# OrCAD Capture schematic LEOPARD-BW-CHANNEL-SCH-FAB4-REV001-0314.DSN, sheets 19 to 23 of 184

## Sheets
19 160_PVTT_EF_MOSFET: size A3; title: PVTT_EF_MOSFET
20 159_PVDDQ_EF_MOSFET: size C; title: PVDDQ_EF_MOSFET
21 158_PVDDQ_EF_Controller: size C; title: PVDQ_EF_CONTROLLER
22 157_PVPP_CD_TPS53318: size A3; title: PVPP_CD_TPS53318
23 156_PVDDQ_CD_Decoupling: size A3; title: PVDDQ_CD_DECOUPLING

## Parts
sheet 156_PVDDQ_CD_Decoupling
PC415  SCD1U25V5KX-1GP  [C805H54]
PC416  SC1U25V6KX-2GP  [C1206H45]
PC417  SCD1U25V5KX-1GP  [C805H54]
PC418  SE470UF2VDM-GP  [CT7343H83]
PC419  SE470UF2VDM-GP  [CT7343H83]
PC420  SE470UF2VDM-GP  [CT7343H83]
PC421  SE470UF2VDM-GP  [CT7343H83]
PC422  SC47U4V5MX-2-GP  [C805H58]
PC423  SC47U4V5MX-2-GP  [C805H58]
PC424  SC47U4V5MX-2-GP  [C805H58]
PC425  SC47U4V5MX-2-GP  [C805H58]
PC426  SC22U6D3V5MX-5-GP  [C805H56]
PC427  SC22U6D3V5MX-5-GP  [C805H56]
PC428  SC22U6D3V5MX-5-GP  [C805H56]
PC429  SC22U6D3V5MX-5-GP  [C805H56]
PC430  SC22U6D3V5MX-5-GP  [C805H56]
PC431  SC22U6D3V5MX-5-GP  [C805H56]
PC432  SC22U6D3V5MX-5-GP  [C805H56]
PC433  SC22U6D3V5MX-5-GP  [C805H56]
PC434  SC22U6D3V5MX-5-GP  [C805H56]
PC435  SC22U6D3V5MX-5-GP  [C805H56]
PC436  SC22U6D3V5MX-5-GP  [C805H56]
PC437  SC22U6D3V5MX-5-GP  [C805H56]
PC438  SC22U6D3V5MX-5-GP  [C805H56]
PC439  SC22U6D3V5MX-5-GP  [C805H56]
PC440  SC22U6D3V5MX-5-GP  [C805H56]
PC441  SC22U6D3V5MX-5-GP  [C805H56]
PC442  SC22U6D3V5MX-5-GP  [C805H56]
PC443  SC22U6D3V5MX-5-GP  [C805H56]
PC444  SC22U6D3V5MX-5-GP  [C805H56]
PC445  SC22U6D3V5MX-5-GP  [C805H56]
PC446  SC22U6D3V5MX-5-GP  [C805H56]
PC447  SC22U6D3V5MX-5-GP  [C805H56]
PC448  SC22U6D3V5MX-5-GP  [C805H56]
PC449  SC22U6D3V5MX-5-GP  [C805H56]
PC450  SC22U6D3V5MX-5-GP  [C805H56]
PC451  SC22U6D3V5MX-5-GP  [C805H56]
PC452  SC22U6D3V5MX-5-GP  [C805H56]
PC453  SC22U6D3V5MX-5-GP  [C805H56]
PC454  SC22U6D3V5MX-5-GP  [C805H56]
PC455  SC22U6D3V5MX-5-GP  [C805H56]
PC456  SC22U6D3V5MX-5-GP  [C805H56]
PC457  SC22U6D3V5MX-5-GP  [C805H56]
PC458  SC22U6D3V5MX-5-GP  [C805H56]
PC459  SC22U6D3V5MX-5-GP  [C805H56]
PC460  SC22U6D3V5MX-5-GP  [C805H56]
PC461  SC22U6D3V5MX-5-GP  [C805H56]
PC462  SC22U6D3V5MX-5-GP  [C805H56]
PC463  SC22U6D3V5MX-5-GP  [C805H56]
PC464  SC22U6D3V5MX-5-GP  [C805H56]
PC465  SC22U6D3V5MX-5-GP  [C805H56]
PC845  SC22U6D3V5MX-5-GP  [C805H56]
PC846  SC22U6D3V5MX-5-GP  [C805H56]
PC847  SC22U6D3V5MX-5-GP  [C805H56]
PC848  SC22U6D3V5MX-5-GP  [C805H56]
PC849  SC22U6D3V5MX-5-GP  [C805H56]
PC850  SC22U6D3V5MX-5-GP  [C805H56]
PC855  SC22U6D3V5MX-5-GP  [C805H56]
PC856  SC22U6D3V5MX-5-GP  [C805H56]
PC997  SC22U6D3V5MX-5-GP  [C805H56]
PC998  SC22U6D3V5MX-5-GP  [C805H56]
PC999  SC22U6D3V5MX-5-GP  [C805H56]
PL22  IND-65NH-GP  [L4038-1412H158]
PR255  33R3F-L-GP  [R603H22]
PR256  0R2F-L-GP  [R402H16]
PR257  0R2F-L-GP  [R402H16]
PTC6  E270U16VM-28-GP  [ECAP-100D6D3H363]
sheet 157_PVPP_CD_TPS53318
PC466  SC10U16V5KX-1-GP  [C805H54]
PC467  SC10U16V5KX-1-GP  [C805H54]
PC468  SC10U16V5KX-1-GP  [C805H54]
PC469  SC10U16V5KX-1-GP  [C805H54]
PC470  SCD1U16V3KX-3GP  [C603H36]
PC471  SC4D7U25V5KX-1-GP  [C805H58]
PC472  SCD1U50V3KX-GP  [C603H36]
PC473  SC2K2P50V3KX-GP  [C603]
PC474  SC1U10V2KX-4-GP  [C402H22]
PC475  SCD1U16V2KX-3GP  [C402H22]
PC476  SC1KP50V2KX-1GP  [C402H22]
PC477  SCD1U16V3KX-3GP  [C603H36]
PC478  SC22U6D3V5MX-5-GP  [C805H56]
PC479  SC47U4V5MX-2-GP  [C805H58]
PC480  SC47U4V5MX-2-GP  [C805H58]
PC481  SC47U4V5MX-2-GP  [C805H58]
PC482  SC47U4V5MX-2-GP  [C805H58]
PC483  SC47U4V5MX-2-GP  [C805H58]
PC484  SC47U4V5MX-2-GP  [C805H58]
PC1039  SC1U10V2KX-4-GP  [C402H22]
PD23  BZT52-C3V3S-GP  [SOD323AKH38]
PL23  BLM21PG220SN1DGP  [L20125H42]
PL24  IND-2D2UH-242-GP  [L7165-1732H119]
PR258  2D2R3-1-U-GP  [R603H22]
PR259  3D01R5F-GP  [R805H24]
PR260  0R2J-2-GP  [R402H16]
PR262  3K9R2F-GP  [R402H16]
PR263  10R3F-GP  [R603H22]
PR264  3D01R5F-GP  [R805H24]
PR265  100KR2F-L1-GP  [R402H16]
PR266  100KR2F-L1-GP  [R402H16]
PR267  100KR2F-L1-GP  [R402H16]
PR268  866KR2F-GP  [R402H16]
PR269  619KR2F-GP  [R402H16]
PR270  31K6R2F-GP  [R402H16]
PR271  10KR2F-2-GP  [R402H16]
PR272  0R3J-0-U-GP  [R603H22]
PR644  10KR2F-2-GP  [R402H16]
PR800  0R2J-2-GP  [R402H16]
PU24  TPS53318DQPR-GP  [DFN22G6050-G6133H60]
sheet 158_PVDDQ_EF_Controller
PC1423  SC1KP50V2KX-1GP  [C402H22]
PC1424  SC1U10V2KX-4-GP  [C402H22]
PC1425  SCD1U16V2KX-3GP  [C402H22]
PC1426  SC1U10V2KX-4-GP  [C402H22]
PC1427  SCD1U16V2KX-3GP  [C402H22]
PC1431  SC220P50V2KX-3GP  [C402H22]
PC1432  SCD47U25V3KX-3-GP  [C603H36]
PC1433  SC220P50V2KX-3GP  [C402H22]
PC1434  SC220P50V2JN-3GP  [C402H22]
PC1468  SC220P50V2JN-3GP  [C402H22]
PC1622  SC220P50V2JN-3GP  [C402H22]
PC7335  SCD47U6D3V2KX-1-GP  [C402H22]
PC7336  SCD47U6D3V2KX-1-GP  [C402H22]
PQ13  NST3906F3T5G-GP-U  [SOT-1123CBE1006-1H16]
PR1940  0R2J-2-GP  [R402H16]
PR2058  19K1R2F-GP  [R402H16]
PR2059  1KR2F-3-GP  [R402H16]
PR2060  0R2J-2-GP  [R402H16]
PR2063  1KR2F-3-GP  [R402H16]
PR2066  1KR2F-3-GP  [R402H16]
PR2067  0R2J-2-GP  [R402H16]
PR2068  0R2J-2-GP  [R402H16]
PR2069  10R3F-GP  [R603H22]
PR2071  0R2J-2-GP  [R402H16]
PR2072  0R0402-PAD-1-GP  [0R0402-PAD]
PR2075  16KR2F-GP  [R402H16]
PR2076  4K02R2F-GP  [R402H16]
PR2077  549R2F-GP  [R402H16]
PR2078  16KR2F-GP  [R402H16]
PR2079  0R2J-2-GP  [R402H16]
PR2080  0R2J-2-GP  [R402H16]
PR2081  150R2F-1-GP  [R402H16]
PR2082  0R2J-2-GP  [R402H16]
PR2083  10R3F-GP  [R603H22]
PR2084  0R0402-PAD-1-GP  [0R0402-PAD]
PTP5  TP20B24R10-B-GP  [TP20B24R10-B]
PU25  PX3244HDM-1-GP  [QFN40J5-G3D75H36]
sheet 159_PVDDQ_EF_MOSFET
PC1546  SCD47U25V3KX-3-GP  [C603H36]
PC1547  SC10U16V5KX-1-GP  [C805H54]
PC1548  SC10U16V5KX-1-GP  [C805H54]
PC1549  SC10U16V5KX-1-GP  [C805H54]
PC1550  SCD1U16V2KX-3GP  [C402H22]
PC1551  SC1U25V3KX-GP  [C603H36]
PC1552  SCD1U16V2KX-3GP  [C402H22]
PC1553  SC1U10V2KX-4-GP  [C402H22]
PC1554  SCD22U16V2KX-GP  [C402H22]
PC1555  SC1U10V2KX-4-GP  [C402H22]
PC1556  SCD47U25V3KX-3-GP  [C603H36]
PC1557  SC10U16V5KX-1-GP  [C805H54]
PC1558  SC10U16V5KX-1-GP  [C805H54]
PC1559  SC10U16V5KX-1-GP  [C805H54]
PC1560  SCD1U16V2KX-3GP  [C402H22]
PC1561  SC1U25V3KX-GP  [C603H36]
PC1562  SCD1U16V2KX-3GP  [C402H22]
PC1563  SC1U10V2KX-4-GP  [C402H22]
PC1564  SCD22U16V2KX-GP  [C402H22]
PC1565  SC1U10V2KX-4-GP  [C402H22]
PG73  COPPER-CLOSE-GP-U  [CON2C-U]
PG74  COPPER-CLOSE-GP-U  [CON2C-U]
PG79  COPPER-CLOSE-GP-U  [CON2C-U]
PG80  COPPER-CLOSE-GP-U  [CON2C-U]
PL88  IND-150NH-15-GP  [L102078-254224H296]
PL95  IND-150NH-15-GP  [L102078-254224H296]
PR38  0R2J-2-GP  [R402H16]
PR39  0R2J-2-GP  [R402H16]
PR56  0R2J-2-GP  [R402H16]
PR57  0R2J-2-GP  [R402H16]
PR2214  1R2F-GP  [R402H16]
PR2249  1R2F-GP  [R402H16]
PR2250  10KR2F-2-GP  [R402H16]
PR2251  10KR2F-2-GP  [R402H16]
PR2271  0R3J-6-GP  [R603H22]
PR2274  0R3J-6-GP  [R603H22]
PR6653  562R2F-GP  [R402H16]
PR6654  562R2F-GP  [R402H16]
PR6667  562R2F-GP  [R402H16]
PR6668  562R2F-GP  [R402H16]
PTP33  TPAD24  [TPAD24]
PTP34  TPAD24  [TPAD24]
PTP47  TPAD24  [TPAD24]
PTP48  TPAD24  [TPAD24]
PU191  TDA21232-GP  [QFN31G5-G4P-7H38]
PU198  TDA21232-GP  [QFN31G5-G4P-7H38]
sheet 160_PVTT_EF_MOSFET
PC518  SC1U10V2KX-4-GP  [C402H22]
PC519  SCD22U16V2KX-GP  [C402H22]
PC521  SCD22U16V2KX-GP  [C402H22]
PC523  SC1U25V3KX-GP  [C603H36]
PC526  SC10U16V5KX-1-GP  [C805H54]
PC527  SC10U16V5KX-1-GP  [C805H54]
PC528  SCD47U25V3KX-3-GP  [C603H36]
PC529  SC220P50V2JN-3GP  [C402H22]
PC530  SC47U4V5MX-2-GP  [C805H58]
PC531  SC47U4V5MX-2-GP  [C805H58]
PC532  SC22U6D3V5MX-5-GP  [C805H56]
PC533  SC22U6D3V5MX-5-GP  [C805H56]
PC534  SC22U6D3V5MX-5-GP  [C805H56]
PC535  SC22U6D3V5MX-5-GP  [C805H56]
PC536  SC22U6D3V5MX-5-GP  [C805H56]
PC537  SC22U6D3V5MX-5-GP  [C805H56]
PC538  SC22U6D3V5MX-5-GP  [C805H56]
PC539  SC22U6D3V5MX-5-GP  [C805H56]
PC540  SC22U6D3V5MX-5-GP  [C805H56]
PC541  SC22U6D3V5MX-5-GP  [C805H56]
PC542  SC22U6D3V5MX-5-GP  [C805H56]
PC543  SC22U6D3V5MX-5-GP  [C805H56]
PC544  SE470UF2VDM-GP  [CT7343H83]
PG37  COPPER-CLOSE-GP-U  [CON2C-U]
PG38  COPPER-CLOSE-GP-U  [CON2C-U]
PL27  IND-1UH-101-GP  [L6868-3612H166]
PQ8  NST3906F3T5G-GP-U  [SOT-1123CBE1006-1H16]
PR318  2D2R2F-GP  [R402H16]
PR320  10KR2F-2-GP  [R402H16]
PR321  93K1R2F-L-GP  [R402H16]
PR324  562R2F-GP  [R402H16]
PR325  562R2F-GP  [R402H16]
PR326  0R2F-L-GP  [R402H16]
PR327  0R2F-L-GP  [R402H16]
PR328  120R3F-L-GP  [R603H22]
PR856  0R3J-0-U-GP  [R603H22]
PR857  0R3J-0-U-GP  [R603H22]
PU28  PX3517-GP  [DFN10G3-G2619H36]
PU29  AON7934-GP  [MLP8F3-G2P-1H32]

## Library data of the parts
PC415 PC417 = SCD1U25V5KX-1GP: CHIP CAP0.1U25V K0805 X7R(ROHS; GREENDFACTOR: R2_SA;HF_SA;G_SA;; Package Type: SMD-BCG; Part Number: 78.10422.21L; SPEC: http://wpqssvr.wistron.com.tw:7001/wpqs/servlet/COM.qpart.Attachment?PartNumber=78.10422.21L
PC416 = SC1U25V6KX-2GP: CHIP CAP C 1U 25V K1206 X7R; GREENDFACTOR: R2_SA;HF_SA;G_SA;; Package Type: SMD-BCG1; Part Number: 78.10522.22L; SPEC: http://wpqssvr.wistron.com.tw:7001/wpqs/servlet/COM.qpart.Attachment?PartNumber=78.10522.22L
PC418-PC421 PC544 = SE470UF2VDM-GP: CHIP CAP 470UF 2V EEFSX0D471X; GREENDFACTOR: R_SA;; Module: VR_DDR_P1V5_VDDQ; Package Type: SMD-TCG1; Part Number: 79.47719.2BL; Part Type: SMD-TCG1; Part_Function: Cout_bulk; Part_Spec: 470uF/2V/6mohm; Part_Type: Solid_al_cap; SPEC: http://wpqssvr.wistron.com.tw:7001/wpqs/servlet/COM.qpart.Attachment?PartNumber=79.47719.2BL; VENDOR_PN: EEFSX0D471XE
PC422-PC425 PC479-PC484 PC530 PC531 = SC47U4V5MX-2-GP: CHIP CAP C 47U 4V M0805 X6S; GREENDFACTOR: R2_SA;HF_SA;G_SA;; Package Type: SMD-BCG3; Part Number: 78.4761T.81L; SPEC: http://wpqssvr.wistron.com.tw:7001/wpqs/servlet/COM.qpart.Attachment?PartNumber=78.4761T.81L
PC426-PC465 PC478 PC532-PC543 PC845-PC850 PC855 PC856 = SC22U6D3V5MX-5-GP: CHIP CAP C 22U 6.3V M0805 X6S; GREENDFACTOR: R2_SA;HF_SA;G_SA;; Package Type: SMD-BCG2; Part Number: 78.22610.81L; SPEC: http://wpqssvr.wistron.com.tw:7001/wpqs/servlet/COM.qpart.Attachment?PartNumber=78.22610.81L
PC997-PC999 = SC22U6D3V5MX-5-GP: CHIP CAP C 22U 6.3V M0805 X6S; GREENDFACTOR: R2_SA;HF_SA;G_SA;; Package Type: SMD-BCG2; Part Number: 78.22610.81L; SPEC: http://wpqssvr.wistron.com.tw:7001/wpqs/servlet/COM.qpart.Attachment?PartNumber=78.22610.81L; Size: 0805; Type: X6S
PL22 = IND-65NH-GP: CHIP IND 65NH FP0404R1-R065-R; GREENDFACTOR: R2_SA;; Part Number: 68.650CN.101; Part Type: DISCRET-G6; SPEC: http://wpqssvr.wistron.com.tw:7001/wpqs/servlet/COM.qpart.Attachment?PartNumber=68.650CN.101
PR255 = 33R3F-L-GP: CHIP RES 33 F 1/10W 0603; GREENDFACTOR: R2_SA;HF_SA;G_SA;; Package Type: SMD-RG; Part Number: 64.33R05.55L; SPEC: http://wpqssvr.wistron.com.tw:7001/wpqs/servlet/COM.qpart.Attachment?PartNumber=64.33R05.55L
PR256 PR257 PR326 PR327 = 0R2F-L-GP: CHIP RES 0 F 0402 RK73Z1ETTP KOA; GREENDFACTOR: R2_SA;; Package Type: SMD-RG5; Part Number: 64.R0005.L0L; SPEC: http://wpqssvr.wistron.com.tw:7001/wpqs/servlet/COM.qpart.Attachment?PartNumber=64.R0005.L0L
PTC6 = E270U16VM-28-GP: CAP EL 270U 16V RT2.5 6.3*8 SOLID CAP; GREENDFACTOR: R2_SA;HF_SA;; Part Number: 09.2771D.E4L; Part Spec: 270uF/16V/10mohm/5A; Part Type: DIP-TCG4; SPEC: http://wpqssvr.wistron.com.tw:7001/wpqs/servlet/COM.qpart.Attachment?PartNumber=09.2771D.E4L
PC466-PC469 PC526 PC527 PC1547-PC1549 PC1557-PC1559 = SC10U16V5KX-1-GP: CHIP CAP C 10U 16V K0805 X6S; GREENDFACTOR: R2_SA;; Package Type: SMD-BCG5; Part Number: 78.10621.81L; SPEC: http://wpqssvr.wistron.com.tw:7001/wpqs/servlet/COM.qpart.Attachment?PartNumber=78.10621.81L
PC470 PC477 = SCD1U16V3KX-3GP: CHIP CAP 0.1U16V K0603 X7R(ROH; GREENDFACTOR: R2_SA;R_SA;HF_SA;G_SA;; Module: VR_SYSTEM_P1V8; Package Type: SMD-BCG; Part Number: 78.10421.2BL; SPEC: http://wpqssvr.wistron.com.tw:7001/wpqs/servlet/COM.qpart.Attachment?PartNumber=78.10421.2BL; Size: 0603; Type: X7R
PC471 = SC4D7U25V5KX-1-GP: CHIP CAP C 4.7U 25V K0805 X7R; GREENDFACTOR: R2_SA;HF_SA;G_SA;; Package Type: SMD-BCG4; Part Number: 078.47522.0211; SPEC: http://wpqssvr.wistron.com.tw:7001/wpqs/servlet/COM.qpart.Attachment?PartNumber=078.47522.0211
PC472 = SCD1U50V3KX-GP: CHIP CAP C 0.1U 50V K0603 X7R; GREENDFACTOR: R2_SA;HF_SA;G_SA;; Level: SMD; MAIN_SOURCE: M; Package Type: RCL_GP; Part Number: 78.10424.2BL; Part Type: RCL_GP; SPEC: http://wpqssvr.wistron.com.tw:7001/wpqs/servlet/COM.qpart.Attachment?PartNumber=78.10424.2BL
PC473 = SC2K2P50V3KX-GP: CHIP CAP C 2200P 50V K0603 X7R; GREENDFACTOR: R2_SA;HF_SA;G_SA;; Level: SMD; POP?: NOPOP; Package Type: SMD-BCG6; Part Number: 78.22224.2BL; Part Type: SMD-BCG6; SPEC: http://wpqssvr.wistron.com.tw:7001/wpqs/servlet/COM.qpart.Attachment?PartNumber=78.22224.2BL; Status: POP
PC474 PC518 PC1424 PC1426 PC1553 PC1555 PC1563 PC1565 = SC1U10V2KX-4-GP: CHIP CAP C 1U 10V K 0402 X6S; GREENDFACTOR: R2_SA;HF_SA;; Package Type: SMD-BCG6; Part Number: 78.10523.8FL; SPEC: http://wpqssvr.wistron.com.tw:7001/wpqs/servlet/COM.qpart.Attachment?PartNumber=78.10523.8FL
PC475 = SCD1U16V2KX-3GP: CHIP CAP C 0.1U 16V K0402 X7R; CATEGORIES: CAP_1.xV; GREENDFACTOR: R2_SA;HF_SA;G_SA;; MAIN_SOURCE: M; Part Number: 78.10421.2FL; Part Type: SMD-BCG; SPEC: http://wpqssvr.wistron.com.tw:7001/wpqs/servlet/COM.qpart.Attachment?PartNumber=78.10421.2FL
PC476 = SC1KP50V2KX-1GP: CHIP CAP 1000P50V K0402 X7R(RO; GREENDFACTOR: R2_SA;HF_SA;G_SA;; Level: SMD; MAIN_SOURCE: M; Package Type: SMD-BCG; Part Number: 78.10224.2FL; Part Type: SMD-BCG; SPEC: http://wpqssvr.wistron.com.tw:7001/wpqs/servlet/COM.qpart.Attachment?PartNumber=78.10224.2FL; Status: POP
PC1039 = SC1U10V2KX-4-GP: CHIP CAP C 1U 10V K 0402 X6S; GREENDFACTOR: R2_SA;HF_SA;; POP?: NOPOP; Package Type: SMD-BCG6; Part Number: 78.10523.8FL; SPEC: http://wpqssvr.wistron.com.tw:7001/wpqs/servlet/COM.qpart.Attachment?PartNumber=78.10523.8FL
PD23 = BZT52-C3V3S-GP: DIODE ZEN BZT52-C3V3S 3.3V SOD-323; GREENDFACTOR: R2_SA;; Part Number: 83.3R303.G3F; Part Type: DISCRET-G4; SPEC: http://wpqssvr.wistron.com.tw:7001/wpqs/servlet/COM.qpart.Attachment?PartNumber=83.3R303.G3F
PL23 = BLM21PG220SN1DGP: CHIP BEAD BLM21PG220SN1D (LF); GREENDFACTOR: R2_SA;HF_SA;; Level: SMD; Package Type: DISCRET-G; Part Number: 68.00084.831; Part Type: DISCRET-G; SPEC: http://wpqssvr.wistron.com.tw:7001/wpqs/servlet/COM.qpart.Attachment?PartNumber=68.00084.831; Status: POP
PL24 = IND-2D2UH-242-GP: CHIP IND 2.2UH M SPM6530T-2R2M; GREENDFACTOR: R2_SA;HF_SA;; Package Type: DISCRET-G6; Part Number: 68.2R21E.10X; SPEC: http://wpqssvr.wistron.com.tw:7001/wpqs/servlet/COM.qpart.Attachment?PartNumber=68.2R21E.10X
PR258 = 2D2R3-1-U-GP: CHIP RES 2.2 F 1/10W 0603(ROHS; GREENDFACTOR: R2_SA;HF_SA;G_SA;; Package Type: RCL_GP; Part Number: 64.2R205.55L; SPEC: http://wpqssvr.wistron.com.tw:7001/wpqs/servlet/COM.qpart.Attachment?PartNumber=64.2R205.55L
PR259 = 3D01R5F-GP: CHIP RES 3.01 F 1/8W 0805; GREENDFACTOR: R2_SA;HF_SA;G_SA;; Level: SMD; Package Type: SMD-RG5; Part Number: 64.3R015.16L; Part Type: SMD-RG5; SPEC: http://wpqssvr.wistron.com.tw:7001/wpqs/servlet/COM.qpart.Attachment?PartNumber=64.3R015.16L; Status: POP
PR260 PR800 = 0R2J-2-GP: CHIP RES 0 J 1/16W 0402; GREENDFACTOR: R2_SA;HF_SA;G_SA;; Level: SMD; Package Type: SMD-RG; Part Number: 63.R0034.1DL; Part Type: SMD-RG; ROOM: VR_CHIPSET; SPEC: http://wpqssvr.wistron.com.tw:7001/wpqs/servlet/COM.qpart.Attachment?PartNumber=63.R0034.1DL; Status: POP
PR262 = 3K9R2F-GP: CHIP RES 3.9K F 1/16W 0402; GREENDFACTOR: R2_SA;HF_SA;G_SA;; Package Type: RCL_GP; Part Number: 64.39015.6DL; SPEC: http://wpqssvr.wistron.com.tw:7001/wpqs/servlet/COM.qpart.Attachment?PartNumber=64.39015.6DL
PR263 PR2069 PR2083 = 10R3F-GP: CHIP RES 10 F 1/10W 0603; GREENDFACTOR: R2_SA;HF_SA;G_SA;; Level: SMD; Package Type: RCL_GP; Part Number: 64.10R05.55L; Part Type: RCL_GP; SPEC: http://wpqssvr.wistron.com.tw:7001/wpqs/servlet/COM.qpart.Attachment?PartNumber=64.10R05.55L; Status: POP
PR264 = 3D01R5F-GP: CHIP RES 3.01 F 1/8W 0805; GREENDFACTOR: R2_SA;HF_SA;G_SA;; Level: SMD; POP?: NOPOP; Package Type: SMD-RG5; Part Number: 64.3R015.16L; Part Type: SMD-RG5; SPEC: http://wpqssvr.wistron.com.tw:7001/wpqs/servlet/COM.qpart.Attachment?PartNumber=64.3R015.16L; Status: POP
PR265 = 100KR2F-L1-GP: CHIP RES 100K F 1/16W 0402; GREENDFACTOR: R2_SA;HF_SA;G_SA;; Part Number: 64.10035.6DL; Part Type: SMD-RG; SPEC: http://wpqssvr.wistron.com.tw:7001/wpqs/servlet/COM.qpart.Attachment?PartNumber=64.10035.6DL
PR266 = 100KR2F-L1-GP: CHIP RES 100K F 1/16W 0402; GREENDFACTOR: R2_SA;HF_SA;G_SA;; Level: SMD; POP?: NOPOP; Package Type: SMD-RG; Part Number: 64.10035.6DL; Part Type: SMD-RG; SPEC: http://wpqssvr.wistron.com.tw:7001/wpqs/servlet/COM.qpart.Attachment?PartNumber=64.10035.6DL; Status: NOPOP
PR267 = 100KR2F-L1-GP: CHIP RES 100K F 1/16W 0402; GREENDFACTOR: R2_SA;HF_SA;G_SA;; Package Type: SMD-RG; Part Number: 64.10035.6DL; SPEC: http://wpqssvr.wistron.com.tw:7001/wpqs/servlet/COM.qpart.Attachment?PartNumber=64.10035.6DL
PR268 = 866KR2F-GP: CHP RES 866K F 1/16W 0402; GREENDFACTOR: R2_SA;HF_SA;G_SA;; Level: SMD; POP?: NOPOP; Package Type: SMD-RG4; Part Number: 64.86635.6DL; Part Type: SMD-RG4; SPEC: http://wpqssvr.wistron.com.tw:7001/wpqs/servlet/COM.qpart.Attachment?PartNumber=64.86635.6DL; Status: POP
PR269 = 619KR2F-GP: CHIP RES 619K F 1/16W 0402; GREENDFACTOR: R2_SA;HF_SA;G_SA;; Level: SMD; POP?: NOPOP; Package Type: SMD-RG3; Part Number: 64.61935.6DL; Part Type: SMD-RG3; SPEC: http://wpqssvr.wistron.com.tw:7001/wpqs/servlet/COM.qpart.Attachment?PartNumber=64.61935.6DL; Status: NOPOP
PR270 = 31K6R2F-GP: CHIP RES 31.6K F 1/16W 0402; GREENDFACTOR: R2_SA;HF_SA;G_SA;; Package Type: RCL_GP; Part Number: 64.31625.6DL; SPEC: http://wpqssvr.wistron.com.tw:7001/wpqs/servlet/COM.qpart.Attachment?PartNumber=64.31625.6DL
PR271 = 10KR2F-2-GP: CHIP RES 10K F 1/16W 0402; GREENDFACTOR: R2_SA;HF_SA;G_SA;; Package Type: SMD-RG; Part Number: 64.10025.6DL; SPEC: http://wpqssvr.wistron.com.tw:7001/wpqs/servlet/COM.qpart.Attachment?PartNumber=64.10025.6DL
PR272 PR856 PR857 = 0R3J-0-U-GP: CHIP RES 0 J 1/10W 0603; GREENDFACTOR: R2_SA;HF_SA;G_SA;; Package Type: RCL_GP; Part Number: 63.00000.00L; SPEC: http://wpqssvr.wistron.com.tw:7001/wpqs/servlet/COM.qpart.Attachment?PartNumber=63.00000.00L
PR644 = 10KR2F-2-GP: CHIP RES 10K F 1/16W 0402; GREENDFACTOR: R2_SA;HF_SA;G_SA;; Level: SMD; Package Type: SMD-RG; Part Number: 64.10025.6DL; Part Type: SMD-RG; SPEC: http://wpqssvr.wistron.com.tw:7001/wpqs/servlet/COM.qpart.Attachment?PartNumber=64.10025.6DL
PU24 = TPS53318DQPR-GP: IC PWR CTRL TPS53318DQPR QFN 22P; GREENDFACTOR: R2_C;HF_C;; Package Type: DISCRET-G5; Part Number: 74.53318.073; SPEC: http://wpqssvr.wistron.com.tw:7001/wpqs/servlet/COM.qpart.Attachment?PartNumber=74.53318.073
PC1423 = SC1KP50V2KX-1GP: CHIP CAP 1000P50V K0402 X7R(RO; GREENDFACTOR: R2_SA;HF_SA;G_SA;; MAIN_SOURCE: M; Package Type: SMD-BCG; Part Number: 78.10224.2FL; SPEC: http://wpqssvr.wistron.com.tw:7001/wpqs/servlet/COM.qpart.Attachment?PartNumber=78.10224.2FL
PC1425 PC1427 = SCD1U16V2KX-3GP: CHIP CAP C 0.1U 16V K0402 X7R; GREENDFACTOR: R2_SA;HF_SA;G_SA;; MAIN_SOURCE: M; Package Type: SMD-BCG; Part Number: 78.10421.2FL; SPEC: http://wpqssvr.wistron.com.tw:7001/wpqs/servlet/COM.qpart.Attachment?PartNumber=78.10421.2FL
PC1431 PC1433 = SC220P50V2KX-3GP: CHIP CAP 220P50V K0402 X7R(ROH; GREENDFACTOR: R2_SA;HF_SA;G_SA;; MAIN_SOURCE: M; Package Type: SMD-BCG; Part Number: 78.22124.2FL; SPEC: http://wpqssvr.wistron.com.tw:7001/wpqs/servlet/COM.qpart.Attachment?PartNumber=78.22124.2FL
PC528 PC1432 PC1546 PC1556 = SCD47U25V3KX-3-GP: CHIP CAP C 0.47U 25V K0603 X7R; GREENDFACTOR: R2_SA;HF_SA;G_SA;; Part Number: 78.47422.2BL; Part Type: SMD-BCG5; SPEC: http://wpqssvr.wistron.com.tw:7001/wpqs/servlet/COM.qpart.Attachment?PartNumber=78.47422.2BL
PC529 PC1434 PC1468 PC1622 = SC220P50V2JN-3GP: CHIP CAP C 220P 50V J0402 NPO; GREENDFACTOR: R2_SA;HF_SA;G_SA;; Package Type: SMD-BCG; Part Number: 78.22134.1FL; SPEC: http://wpqssvr.wistron.com.tw:7001/wpqs/servlet/COM.qpart.Attachment?PartNumber=78.22134.1FL
PC7335 PC7336 = SCD47U6D3V2KX-1-GP: CHIP CAP C 0.47U 6.3V K 0402 X6S; GREENDFACTOR: R2_SA;HF_SA;; Package Type: SMD-BCG3; Part Number: 78.47420.8FL; SPEC: http://wpqssvr.wistron.com.tw:7001/wpqs/servlet/COM.qpart.Attachment?PartNumber=78.47420.8FL
PQ8 PQ13 = NST3906F3T5G-GP-U: XTOR NST3906F3T5G PNP SOT-1123; GREENDFACTOR: R2_SA;HF_SA;; Package Type: DISCRET-G5; Part Number: 84.03906.01K; SPEC: http://wpqssvr.wistron.com.tw:7001/wpqs/servlet/COM.qpart.Attachment?PartNumber=84.03906.01K
PR1940 PR2082 = 0R2J-2-GP: CHIP RES 0 J 1/16W 0402; GREENDFACTOR: R2_SA;HF_SA;G_SA;; Part Number: 63.R0034.1DL; Part Type: SMD-RG; SPEC: http://wpqssvr.wistron.com.tw:7001/wpqs/servlet/COM.qpart.Attachment?PartNumber=63.R0034.1DL
PR2058 = 19K1R2F-GP: CHIP RES 19.1K F 1/16W 0402; GREENDFACTOR: R2_SA;HF_SA;G_SA;; Part Number: 64.19125.6DL; Part Type: RCL_GP; SPEC: http://wpqssvr.wistron.com.tw:7001/wpqs/servlet/COM.qpart.Attachment?PartNumber=64.19125.6DL
PR2059 PR2063 PR2066 = 1KR2F-3-GP: CHIP RES 1K F 1/16W 0402; GREENDFACTOR: R2_SA;HF_SA;G_SA;; Package Type: SMD-RG; Part Number: 64.10015.6DL; SPEC: http://wpqssvr.wistron.com.tw:7001/wpqs/servlet/COM.qpart.Attachment?PartNumber=64.10015.6DL
PR56 PR57 PR2060 PR2067 PR2068 PR2071 PR2079 PR2080 = 0R2J-2-GP: CHIP RES 0 J 1/16W 0402; GREENDFACTOR: R2_SA;HF_SA;G_SA;; Package Type: SMD-RG; Part Number: 63.R0034.1DL; SPEC: http://wpqssvr.wistron.com.tw:7001/wpqs/servlet/COM.qpart.Attachment?PartNumber=63.R0034.1DL
PR2072 PR2084 = 0R0402-PAD-1-GP: DUMMY PAD WITH WIRE RES 0 0402; GREENDFACTOR: R_C;; Module: VR_CPU_PVCC; Package Type: SMD-RG2; Part Number: ZZ.R0402.001; Part Type: SMD-RG2; Quotation: 8_1; SPEC: http://wpqssvr.wistron.com.tw:7001/wpqs/servlet/COM.qpart.Attachment?PartNumber=ZZ.R0402.001
PR2075 = 16KR2F-GP: CHIP RES 16K F 1/16W 0402; GREENDFACTOR: R2_SA;HF_SA;G_SA;; Module: VR_PVCORE_CPU; POP?: NOPOP; Package Type: SMD-RG; Part Number: 64.16025.6DL; Quotation: 8_1; SPEC: http://wpqssvr.wistron.com.tw:7001/wpqs/servlet/COM.qpart.Attachment?PartNumber=64.16025.6DL
PR2076 = 4K02R2F-GP: CHIP RES 4.02K F 1/16W 0402; GREENDFACTOR: R2_SA;HF_SA;G_SA;; Package Type: RCL_GP; Part Number: 64.40215.6DL; SPEC: http://wpqssvr.wistron.com.tw:7001/wpqs/servlet/COM.qpart.Attachment?PartNumber=64.40215.6DL
PR2077 = 549R2F-GP: CHIP RES 549 F 1/16W 0402; GREENDFACTOR: R2_SA;HF_SA;; Package Type: RCL_GP; Part Number: 64.54905.6DL; SPEC: http://wpqssvr.wistron.com.tw:7001/wpqs/servlet/COM.qpart.Attachment?PartNumber=64.54905.6DL
PR2078 = 16KR2F-GP: CHIP RES 16K F 1/16W 0402; GREENDFACTOR: R2_SA;HF_SA;G_SA;; Module: VR_PVCORE_CPU; Package Type: SMD-RG; Part Number: 64.16025.6DL; Quotation: 8_1; SPEC: http://wpqssvr.wistron.com.tw:7001/wpqs/servlet/COM.qpart.Attachment?PartNumber=64.16025.6DL
PR2081 = 150R2F-1-GP: CHIP RES 150 F 1/16W 0402; GREENDFACTOR: R2_SA;HF_SA;G_SA;; Package Type: SMD-RG; Part Number: 64.15005.6DL; SPEC: http://wpqssvr.wistron.com.tw:7001/wpqs/servlet/COM.qpart.Attachment?PartNumber=64.15005.6DL
PTP5 = TP20B24R10-B-GP_4: TEST VIA FOR DRILL 10MIL; GREENDFACTOR: R2_C;; Package Type: DISCRET-G5; Part Number: ZZ.0TPAD.211; SPEC: http://wpqssvr.wistron.com.tw:7001/wpqs/servlet/COM.qpart.Attachment?PartNumber=ZZ.0TPAD.211
PU25 = PX3244HDM-1-GP: IC CONVERTER PX3244HDM QFN 40P; GREENDFACTOR: R2_SA;; Part Number: 074.03244.0043; Part Type: ASIC-G5; SPEC: http://wpqssvr.wistron.com.tw:7001/wpqs/servlet/COM.qpart.Attachment?PartNumber=074.03244.0043
PC1550 PC1552 PC1560 PC1562 = SCD1U16V2KX-3GP: CHIP CAP C 0.1U 16V K0402 X7R; GREENDFACTOR: R2_SA;HF_SA;G_SA;; MAIN_SOURCE: M; Package Type: SMD-BCG; Part Number: 78.10421.2FL; SPEC: http://wpqssvr.wistron.com.tw:7001/wpqs/servlet/COM.qpart.Attachment?PartNumber=78.10421.2FL; Size: 0402; Type: X7R
PC523 PC1551 PC1561 = SC1U25V3KX-GP: CHIP CAP C 1U 25V K0603 X7R; GREENDFACTOR: R2_SA;HF_SA;G_SA;; Package Type: SMD-BCG; Part Number: 78.10522.2BL; SPEC: http://wpqssvr.wistron.com.tw:7001/wpqs/servlet/COM.qpart.Attachment?PartNumber=78.10522.2BL
PC519 PC521 PC1554 PC1564 = SCD22U16V2KX-GP: CHIP CAP C 0.22U 16V K0402 X7R; GREENDFACTOR: R2_SA;HF_SA;G_SA;; Package Type: SMD-BCG4; Part Number: 78.22421.2FL; SPEC: http://wpqssvr.wistron.com.tw:7001/wpqs/servlet/COM.qpart.Attachment?PartNumber=78.22421.2FL; Size: 0402; Type: X7R
PG37 PG38 PG73 PG74 PG79 PG80 = COPPER-CLOSE-GP-U: COPPER CLOSE; GREENDFACTOR: Regular;; Package Type: DISCRET-G9; Part Number: ZZ.CON2C.XXX; SPEC: http://wpqssvr.wistron.com.tw:7001/wpqs/servlet/COM.qpart.Attachment?PartNumber=ZZ.CON2C.XXX
PL88 PL95 = IND-150NH-15-GP: CHIP IND 150NH K FP1007R3-R15-R; GREENDFACTOR: R2_SA;; Part Number: 68.1512N.10E; Part Type: DISCRET-G9; SPEC: http://wpqssvr.wistron.com.tw:7001/wpqs/servlet/COM.qpart.Attachment?PartNumber=68.1512N.10E
PR38 PR39 = 0R2J-2-GP: CHIP RES 0 J 1/16W 0402; GREENDFACTOR: R2_SA;HF_SA;G_SA;; POP?: NOPOP; Package Type: SMD-RG; Part Number: 63.R0034.1DL; SPEC: http://wpqssvr.wistron.com.tw:7001/wpqs/servlet/COM.qpart.Attachment?PartNumber=63.R0034.1DL
PR2214 PR2249 = 1R2F-GP: CHIP RES 1 F 1/16W 0402; GREENDFACTOR: R2_SA;HF_SA;G_SA;; Package Type: SMD-RG; Part Number: 64.1R005.6DL; SPEC: http://wpqssvr.wistron.com.tw:7001/wpqs/servlet/COM.qpart.Attachment?PartNumber=64.1R005.6DL
PR320 PR2250 PR2251 = 10KR2F-2-GP: CHIP RES 10K F 1/16W 0402; GREENDFACTOR: R2_SA;HF_SA;G_SA;; POP?: NOPOP; Package Type: SMD-RG; Part Number: 64.10025.6DL; SPEC: http://wpqssvr.wistron.com.tw:7001/wpqs/servlet/COM.qpart.Attachment?PartNumber=64.10025.6DL
PR2271 PR2274 = 0R3J-6-GP: CHIP RES 0 J 1/10W 0603; GREENDFACTOR: R2_SA;HF_SA;G_SA;; Part Number: 63.R0033.15L; Part Type: SMD-RG1; SPEC: http://wpqssvr.wistron.com.tw:7001/wpqs/servlet/COM.qpart.Attachment?PartNumber=63.R0033.15L
PR324 PR325 PR6653 PR6654 PR6667 PR6668 = 562R2F-GP: CHIP RES 562 F 1/16W 0402; GREENDFACTOR: R2_SA;HF_SA;G_SA;; Package Type: SMD-RG; Part Number: 64.56205.6DL; SPEC: http://wpqssvr.wistron.com.tw:7001/wpqs/servlet/COM.qpart.Attachment?PartNumber=64.56205.6DL
PTP33 PTP34 PTP47 PTP48 = TPAD24: 24 MILS TEST PAD; GREENDFACTOR: Regular;; Package Type: DISCRET2; Part Number: ZZ.PAD24.001; SPEC: http://wpqssvr.wistron.com.tw:7001/wpqs/servlet/COM.qpart.Attachment?PartNumber=ZZ.PAD24.001
PU191 PU198 = TDA21232-GP: IC PWM TDA21232 IQFN 32P; GREENDFACTOR: R2_C;; Part Number: 074.21232.0073; Part Type: DISCRET-GB1; SPEC: http://wpqssvr.wistron.com.tw:7001/wpqs/servlet/COM.qpart.Attachment?PartNumber=074.21232.0073
PL27 = IND-1UH-101-GP: CHIP IND 1UH HCP0704-1R0-R; GREENDFACTOR: R2_SA;; Package Type: DISCRET-G6; Part Number: 68.1R090.10B; Part_Spec: 1.0uH/6.2mohm/17A; SPEC: http://wpqssvr.wistron.com.tw:7001/wpqs/servlet/COM.qpart.Attachment?PartNumber=68.1R090.10B; Vendor_PN: HCP0704-1R0-R
PR318 = 2D2R2F-GP: CHIP RES 2.2 F 1/16W 0402; GREENDFACTOR: R2_SA;HF_SA;G_SA;; Package Type: SMD-RG1; Part Number: 64.2R205.6DL; SPEC: http://wpqssvr.wistron.com.tw:7001/wpqs/servlet/COM.qpart.Attachment?PartNumber=64.2R205.6DL
PR321 = 93K1R2F-L-GP: CHIP RES 93.1K F 1/16W 0402; GREENDFACTOR: R2_SA;HF_SA;G_SA;; Package Type: SMD-RG; Part Number: 64.93125.6DL; SPEC: http://wpqssvr.wistron.com.tw:7001/wpqs/servlet/COM.qpart.Attachment?PartNumber=64.93125.6DL
PR328 = 120R3F-L-GP: CHIP RES 120 F 1/10W 0603; GREENDFACTOR: R2_SA;HF_SA;G_SA;; Package Type: SMD-RG; Part Number: 64.12005.55L; SPEC: http://wpqssvr.wistron.com.tw:7001/wpqs/servlet/COM.qpart.Attachment?PartNumber=64.12005.55L
PU28 = PX3517-GP: IC MOS DRV PX3517 DFN 10P; GREENDFACTOR: R2_C;; Module: VR_PVCORE_CPU; Package Type: DISCRET-G9; Part Number: 74.03517.0E3; Quotation: 8_1; SPEC: http://wpqssvr.wistron.com.tw:7001/wpqs/servlet/COM.qpart.Attachment?PartNumber=74.03517.0E3
PU29 = AON7934-GP: FET MOS AON7934 NC POWER DFN3X3A; GREENDFACTOR: R2_SA;HF_SA;; Part Number: 84.07934.037; Part Type: DISCRET-G7; SPEC: http://wpqssvr.wistron.com.tw:7001/wpqs/servlet/COM.qpart.Attachment?PartNumber=84.07934.037

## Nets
AGND_PVPP_CD: PR266.1 PR267.1 PR269.1 PR271.2 PR272.1 PR800.2
GND: PC415.2 PC416.2 PC417.2 PC418.2 PC419.2 PC420.2 PC421.2 PC422.2 PC423.2 PC424.2 PC425.2 PC426.2 PC427.2 PC428.2 PC429.2 PC430.2 PC431.2 PC432.2 PC433.2 PC434.2 PC435.2 PC436.2 PC437.2 PC438.2 PC439.2 PC440.2 PC441.2 PC442.2 PC443.2 PC444.2 PC445.2 PC446.2 PC447.2 PC448.2 PC449.2 PC450.2 PC451.2 PC452.2 PC453.2 PC454.2 PC455.2 PC456.2 PC457.2 PC458.2 PC459.2 PC460.2 PC461.2 PC462.2 PC463.2 PC464.2 PC465.2 PC466.2 PC467.2 PC468.2 PC469.2 PC470.2 PC471.2 PC474.1 PC477.2 PC478.2 PC479.2 PC480.2 PC481.2 PC482.2 PC483.2 PC484.2 PC518.2 PC519.2 PC521.2 PC523.2 PC526.2 PC527.2 PC529.1 PC530.2 PC531.2 PC532.2 PC533.2 PC534.2 PC535.2 PC536.2 PC537.2 PC538.2 PC539.2 PC540.2 PC541.2 PC542.2 PC543.2 PC544.2 PC845.2 PC846.2 PC847.2 PC848.2 PC849.2 PC850.2 PC855.2 PC856.2 PC997.2 PC998.2 PC999.2 PC1039.1 PC1423.2 PC1424.2 PC1425.2 PC1426.2 PC1427.2 PC1434.1 PC1468.1 PC1547.2 PC1548.2 PC1549.2 PC1550.2 PC1551.2 PC1552.2 PC1553.1 PC1554.1 PC1555.1 PC1557.2 PC1558.2 PC1559.2 PC1560.2 PC1561.2 PC1562.2 PC1563.1 PC1564.1 PC1565.1 PC1622.1 PD23.A(ANODE) PQ8.B PQ8.C PQ13.B PQ13.C PR38.2 PR39.2 PR255.2 PR257.1 PR264.2 PR272.2 PR321.1 PR327.1 PR328.2 PR2059.2 PR2075.1 PR2076.1 PR2078.1 PTC6.2 PU24.23(GND) PU25.1(BVR_READY) PU25.22(ISEN3N) PU25.37(DNC#37) PU25.41(GND) PU28.5(GND) PU28.11(GND) PU29.5(S2#5) PU29.6(S2#6) PU29.7(S2#7) PU191.4(AGND) PU191.12(PGND) PU191.13(PGND) PU191.14(PGND) PU191.15(PGND) PU191.28(PGND) PU191.32(PGND) PU191.34(PGND) PU198.4(AGND) PU198.12(PGND) PU198.13(PGND) PU198.14(PGND) PU198.15(PGND) PU198.28(PGND) PU198.32(PGND) PU198.34(PGND) ; also on sheet 1 2 3 4 5 6 7 8 9 10 11 12 13 14 15 16 17 18 24 25 26 27 28 29 30 31 32 33 34 35 36 37 38 39 44 46 47 49 50 51 52 53 54 55 56 57 58 59 60 61 62 63 64 65 66 69 70 71 73 74 75 76 78 79 80 81 82 83 84 86 87 88 89 90 91 92 93 94 95 96 97 98 99 100 101 102 103 104 105 106 107 108 109 110 111 112 113 114 115 116 117 118 119 128 129 138 139 159 160 161 166 168 169 170 171 172 173 174 175 176 177 180 181 182 183 184
P3V3_STBY: PR56.2 PR57.2 PR644.1 PR2060.1 PR2063.1 PR2066.1 ; also on sheet 2 3 5 6 8 9 10 11 12 15 16 17 25 26 27 30 31 33 34 35 37 38 39 45 47 49 50 51 52 54 55 59 60 61 62 63 64 65 66 69 70 71 72 73 74 76 79 83 84 87 88 89 90 91 92 93 94 95 96 97 98 99 159 161 166 168 173 174 176 177 179 180 182 183 184
P5V_STBY: PC1554.2 PC1555.2 PC1564.2 PC1565.2 PR318.1 PR2214.1 PR2249.1 PU191.29(PVCC) PU198.29(PVCC) ; also on sheet 4 5 6 8 14 15 24 25 29 30 33 34 37 38 59 61 65 69 76 95
P12V_STBY: PC415.1 PC416.1 PL22.1 PL23.1 PR258.1 ; also on sheet 2 3 4 7 9 10 11 12 13 17 18 27 28 32 36 59 60 75 95 104 105 106 107 108 109 110 111 112 113 114 115 116 117 118 119
PVDDQ_CD: PC418.1 PC419.1 PC420.1 PC421.1 PC422.1 PC423.1 PC424.1 PC425.1 PC426.1 PC427.1 PC428.1 PC429.1 PC430.1 PC431.1 PC432.1 PC433.1 PC434.1 PC435.1 PC436.1 PC437.1 PC438.1 PC439.1 PC440.1 PC441.1 PC442.1 PC443.1 PC444.1 PC445.1 PC446.1 PC447.1 PC448.1 PC449.1 PC450.1 PC451.1 PC452.1 PC453.1 PC454.1 PC455.1 PC456.1 PC457.1 PC458.1 PC459.1 PC460.1 PC461.1 PC462.1 PC463.1 PC464.1 PC465.1 PC845.1 PC846.1 PC847.1 PC848.1 PC849.1 PC850.1 PC855.1 PC856.1 PC997.1 PC998.1 PC999.1 PR255.1 PR256.1 ; also on sheet 25 45 97 112 113 114 115 130 139
PVDDQ_CD_VIN: PC417.1 PL22.2 PTC6.1 ; also on sheet 24 25 26
PVDDQ_CD_VSENN_R: PR257.2 ; also on sheet 26
PVDDQ_CD_VSENP_R: PR256.2 ; also on sheet 26
PVDDQ_EF: PG79.2 PG80.2 PL88.2(F) PL95.2(F) ; also on sheet 18 45 97 108 109 110 111 120 129
PVDDQ_EF_ALERT: PR2079.1 PU25.13(ALERT#)
PVDDQ_EF_BOOT1: PR2271.1 PU191.5(BOOT)
PVDDQ_EF_BOOT2: PR2274.1 PU198.5(BOOT)
PVDDQ_EF_EN: PR2067.2 PU25.8(VR_EN)
PVDDQ_EF_EN1: PR56.1 PU191.31(EN)
PVDDQ_EF_EN2: PR57.1 PU198.31(EN)
PVDDQ_EF_FAULT: PR2071.1 PU25.38(FAULT1)
PVDDQ_EF_GH1: PTP34.1 PU191.6(GH)
PVDDQ_EF_GH2: PTP48.1 PU198.6(GH)
PVDDQ_EF_GL1: PTP33.1 PU191.27(GL#27)
PVDDQ_EF_GL2: PTP47.1 PU198.27(GL#27)
PVDDQ_EF_IMON: PTP5.1 PU25.20(IMON/FAULT2)
PVDDQ_EF_ISEN1N: PC7335.2 PR6654.2 PU25.28(ISEN1N)
PVDDQ_EF_ISEN1P: PC7335.1 PG80.1 PU25.29(ISEN1P)
PVDDQ_EF_ISEN2N: PC7336.2 PR6668.2 PU25.25(ISEN2N)
PVDDQ_EF_ISEN2P: PC7336.1 PG79.1 PU25.26(ISEN2P)
PVDDQ_EF_PG: PR2066.2 PR2068.2 PU25.7(VR_READY)
PVDDQ_EF_PHASE1: PC1556.2 PU191.7(PHASE)
PVDDQ_EF_PHASE1_R: PC1556.1 PR2271.2
PVDDQ_EF_PHASE2: PC1546.2 PU198.7(PHASE)
PVDDQ_EF_PHASE2_R: PC1546.1 PR2274.2
PVDDQ_EF_PWM1: PU25.4(PWM1) PU191.1(PWM)
PVDDQ_EF_PWM2: PU25.5(PWM2) PU198.1(PWM)
PVDDQ_EF_SADDR_L: PR2076.2 PU25.24(SADDR_L)
PVDDQ_EF_SADDR_M: PR2075.2 PU25.21(SADDR_M)
PVDDQ_EF_SW#1: PG73.2 PL88.1(S) PU191.16(SW#16) PU191.17(SW#17) PU191.18(SW#18) PU191.19(SW#19) PU191.20(SW#20) PU191.21(SW#21) PU191.22(SW#22) PU191.23(SW#23) PU191.24(NC#24) PU191.25(NC#25) PU191.26(NC#26)
PVDDQ_EF_SW#1_N: PG73.1 PR6653.2
PVDDQ_EF_SW#1_R: PR6653.1 PR6654.1
PVDDQ_EF_SW#2: PG74.2 PL95.1(S) PU198.16(SW#16) PU198.17(SW#17) PU198.18(SW#18) PU198.19(SW#19) PU198.20(SW#20) PU198.21(SW#21) PU198.22(SW#22) PU198.23(SW#23) PU198.24(NC#24) PU198.25(NC#25) PU198.26(NC#26)
PVDDQ_EF_SW#2_N: PG74.1 PR6667.2
PVDDQ_EF_SW#2_R: PR6667.1 PR6668.1
PVDDQ_EF_TMON1: PR38.1 PU191.30(PHFLT#)
PVDDQ_EF_TMON2: PR39.1 PU198.30(PHFLT#)
PVDDQ_EF_TSEN: PC1622.2 PR1940.1 PU25.27(TSEN)
PVDDQ_EF_TSEN_R: PC1468.2 PQ13.E PR1940.2
PVDDQ_EF_VADDR: PR2078.2 PU25.17(VADDR)
PVDDQ_EF_VCC1: PC1563.2 PR2214.2 PR2251.2 PU191.3(VCC)
PVDDQ_EF_VCC2: PC1553.2 PR2249.2 PR2250.2 PU198.3(VCC)
PVDDQ_EF_VCLK: PR2081.1 PU25.11(VCLK)
PVDDQ_EF_VD15: PC1426.1 PC1427.1 PU25.40(VD15)
PVDDQ_EF_VDD: PC1424.1 PC1425.1 PR2060.2 PU25.31(VDD)
PVDDQ_EF_VDIO: PR2080.1 PU25.12(VDIO)
PVDDQ_EF_VIN: PC521.1 PC523.1 PC526.1 PC527.1 PC1547.1 PC1548.1 PC1549.1 PC1550.1 PC1551.1 PC1552.1 PC1557.1 PC1558.1 PC1559.1 PC1560.1 PC1561.1 PC1562.1 PR2058.2 PU29.2(D1#2) PU29.3(D1#3) PU29.4(D1#4) PU29.9(D1#9) PU191.8(VIN) PU191.9(VIN) PU191.10(VIN) PU191.11(VIN) PU191.33(VIN) PU198.8(VIN) PU198.9(VIN) PU198.10(VIN) PU198.11(VIN) PU198.33(VIN) ; also on sheet 18
PVDDQ_EF_VINSEN: PC1423.1 PR2058.1 PR2059.1 PU25.30(VINSEN)
PVDDQ_EF_VSENN: PC1431.2 PR2072.2 PU25.19(VSENN)
PVDDQ_EF_VSENN_R: PR2072.1 ; also on sheet 18
PVDDQ_EF_VSENP: PC1431.1 PR2069.1 PU25.18(VSENP)
PVDDQ_EF_VSENP_R: PR2069.2 ; also on sheet 18
PVDDQ_EF_ZCD#1: PR2251.1 PU191.2(NC#2)
PVDDQ_EF_ZCD#2: PR2250.1 PU198.2(NC#2)
FM_VPP_MEM_ABCD_EN: PR260.1 ; also on sheet 27 51
IRQ_PVDDQ_EF_VRHOT_LVT3_N: PR2063.2 PU25.39(VR_HOT#) ; also on sheet 177 181
PVPP_CD: PC475.1 PC477.1 PC478.1 PC479.1 PC480.1 PC481.1 PC482.1 PC483.1 PC484.1 PD23.K(CATHODE) PL24.2(F) PR263.1 ; also on sheet 112 113 114 115 160
PVPP_CD_EN: PC1039.2 PR260.2 PU24.2(EN)
PVPP_CD_LL: PC472.2 PC473.1 PL24.1(S) PR262.1 PU24.6(LL#6) PU24.7(LL#7) PU24.8(LL#8) PU24.9(LL#9) PU24.10(LL#10) PU24.11(LL#11)
PVPP_CD_LL_R: PC475.2 PC476.1 PR262.2
PVPP_CD_MODE: PR265.1 PR266.2 PU24.20(MODE)
PVPP_CD_PWRGD: PR265.2 PR644.2 PU24.3(PGOOD) ; also on sheet 26
PVPP_CD_RF: PR268.2 PR269.2 PU24.22(RF)
PVPP_CD_ROVP: PR800.1 PU24.5(ROVP)
PVPP_CD_SNB: PC473.2 PR264.1
PVPP_CD_TRIP: PR267.2 PU24.21(TRIP)
PVPP_CD_VBST: PR259.1 PU24.4(VBST)
PVPP_CD_VBST_RC: PC472.1 PR259.2
PVPP_CD_VDD: PC471.1 PR258.2 PU24.19(VDD)
PVPP_CD_VFB: PC476.2 PR270.1 PR271.1 PU24.1(VFB)
PVPP_CD_VFB_R: PR263.2 PR270.2
PVPP_CD_VIN: PC466.1 PC467.1 PC468.1 PC469.1 PC470.1 PL23.2 PU24.12(VIN) PU24.13(VIN) PU24.14(VIN) PU24.15(VIN) PU24.16(VIN) PU24.17(VIN)
PVPP_CD_VREG: PC474.2 PR268.1 PU24.18(VREG)
PVPP_EF_PWRGD: PR2067.1 ; also on sheet 17
PVTT_EF: PC530.1 PC531.1 PC532.1 PC533.1 PC534.1 PC535.1 PC536.1 PC537.1 PC538.1 PC539.1 PC540.1 PC541.1 PC542.1 PC543.1 PC544.1 PG38.2 PL27.2(S) PR326.1 PR328.1 ; also on sheet 108 109 110 111
PVTT_EF_BISEN_N: PR324.2 PR325.1
PVTT_EF_BISEN_N_R: PG37.1 PR324.1
PVTT_EF_BISENN: PC1432.2 PR325.2 PR2077.2 PU25.33(BISENN)
PVTT_EF_BISENP: PC1432.1 PG38.1 PR2077.1 PU25.34(BISENP)
PVTT_EF_BPWM: PU25.2(BPWM) PU28.4(PWM)
PVTT_EF_BST: PC528.1 PU28.2(BOOT)
PVTT_EF_BTSEN: PC1434.2 PR2082.2 PU25.32(BTSEN)
PVTT_EF_BTSEN_R: PC529.2 PQ8.E PR2082.1
PVTT_EF_BVSENN: PC1433.2 PR2084.2 PU25.35(BVSENN)
PVTT_EF_BVSENP: PC1433.1 PR2083.1 PU25.36(BVSENP)
PVTT_EF_LGATE: PR856.2 PU28.6(LGATE)
PVTT_EF_LGATE_R: PR856.1 PU29.8(G2)
PVTT_EF_PH: PC528.2 PG37.2 PL27.1(F) PR320.2 PU28.10(PHASE) PU29.10(S1/D2)
PVTT_EF_PVCC: PC518.1 PC519.1 PR318.2 PU28.7(VCC) PU28.9(PVCC)
PVTT_EF_RT: PR321.2 PU28.8(RT)
PVTT_EF_UGATE: PR320.1 PR857.2 PU28.1(UGATE)
PVTT_EF_UGATE_R: PR857.1 PU29.1(G1)
PVTT_EF_VSENN_R: PR327.2 PR2084.1
PVTT_EF_VSENP_R: PR326.2 PR2083.2
PWRGD_PVPP_PVDDQ_EF: PR2068.1 ; also on sheet 51
SMB_VR_STBY_LVC3_CLK: PU25.10(SCL) ; also on sheet 16 26 31 35 39 74 161
SMB_VR_STBY_LVC3_DATA: PU25.9(SDA) ; also on sheet 16 26 31 35 39 74 161
SVID_ALERT_CPU1_N: PR2079.2 ; also on sheet 16 35 129
SVID_CLK_CPU1: PR2081.2 ; also on sheet 16 35 129
SVID_DIO_CPU1: PR2080.2 ; also on sheet 16 35 129
VR_FAIL_PVCC_CPU_N: PR2071.2 ; also on sheet 16 26 31 35 39 74

Not connected (* = marked no-connect by the designer): PU25 3(DR_EN)* 6(PWM3)* 14(RESET#)* 15(DNC#15)* 16(DNC#16)* 23(ISEN3P)*; PU28 3(THW#)*; PU191 35(GL#35)*; PU198 35(GL#35)*

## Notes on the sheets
sheet 19
- Power rail : PVTT_EF
  Controller : PX3244H+PX3517+BSZ0907
  TDC : 2A
  Max : 3.6A
  OCP : 6A
  Sinking/Souring : +/-1.14A
  Max Transient Sinking : -1.02A
  Max Transient Sourcing : +0.46A
  Slew rate : 4.67A
  Step Size : 1.48A
- FAB1 REV013 20150413
- Change to 63.00000.00L
- FAB1 REV008 20150326
- Differential Pair
- Place near PL27
- Differential Pair
- Place at the middle of the central DIM
- Routed As Differential Pair
- Place After Lout
- Memory Slot Capacitors
- Place Capcitors Under Output Inductors on Bottom Side
sheet 20
- PVDDQ_EF_MOSFET
- FP1007R3-R15-R
  150nH/0.29mohm/61A
  7.8*10.2*7.3 mm
- FP1007R3-R15-R
  150nH/0.29mohm/61A
  7.8*10.2*7.3 mm
sheet 21
- Power rail : PVDDQ_EF
  Controller : PX3244H
  Min current : 2.59A
  TDC : 36.93A
  Max : 37.87A
  Step Size : 35.28A
  Slew rate : 16.72 A/us
  OCP : 46A
  I2C address : 10
  SVID address : 02
  DDR Type : LR-DIMM
  Level : DDR4
  Process (nm Technology) : 2x
  Physical Rank : 4
  DRAM width : x4
  Speed (MHz) : 2400
  DRAM tech : 4Gb
  DPC (DIMM Per Channel) : 2
  Page : open
  Burst Length : 8
  # of CH/Skt used :4
  Refresh : 2x
  # Memory CHs/VR for VDD/VTT : 2
  # Memory CHs/VR for VPP : 2
- Routed As Differential Pair
- close Phase 1 between phase 2
- Routed As Differential Pair
- VDDQ Measurement point for Bode
- Routed As Differential Pair
- PVDDQ_EF I2C address:10
- Routed As Differential Pair
- Use Daisy Chain
- PDG P.252
- PVDDQ_EF SVID address:02
- Vtt Measurement point for Bode
- Routed As Differential Pair
- Routed As Differential Pair
sheet 22
- Power rail : PVPP_CD(2V5)
  Controller : TPS53318 (Fswitching=500KHz)
  TDC : 3.24A
  MAX : 6.6A
  OCP : 8.5A
- I_rated=6A
  DCR=20mohm
  Z=22ohm
- TDK SPM6530T-2R2M
  L=2.2uH, DCR=17.3 mohm,
- FCCM Mode
- SS=5.6ms
- OCP = 8.5A
- FS=500KHz
- Vout=0.6x(1+Ru/Rd)=2.496
sheet 23
- PVDDQ_CD Decoupling
- PVDDQ_CD LC Filter
- Place Capcitors Under Output Inductors on Bottom Side
- Place After Lout
- Place in CPU Socket Cavity
- Routed As Differential Pair
- Memory Slot Capacitors
